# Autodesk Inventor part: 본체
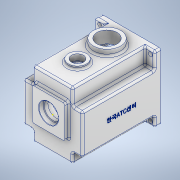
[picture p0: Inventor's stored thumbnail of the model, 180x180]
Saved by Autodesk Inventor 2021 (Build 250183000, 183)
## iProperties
Created: 2022-08
Part Number: 본체
Material: 알루미늄 6061
Document SubType Name: Modeling
Designer: Owner
Mass: 1403.85 g
Surface Area: 1175.53 cm^2
Volume: 519.945 cm^3
Density: 2.7 g/cm^3
Appearance: 알루미늄 - 평지
Author: Owner
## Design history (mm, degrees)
sketch "스케치1"
  geometry: L1 (-49, -55)-(49, -55); L2 (49, -55)-(49, 55); L3 (49, 55)-(-49, 55); L4 (-49, 55)-(-49, -55); L5 (-49, -55)-(49, 55); L6 (49, -55)-(-49, 55); 1 further point
  constraints: 12 end point, 2 midpoint, 2 parallel, 1 horizontal, 1 perpendicular
  dimensions: "d0" = 110 distance between parallel lines of L1 L3; "d1" = 98 distance between parallel lines of L2 L4
extrude "돌출1" new body sketch "스케치1" distance "d2" = 130; taper "d3" = 0 deg
sketch "스케치2"
  geometry: L1 (-49, -55)-(-49, 55) reference; L2 (-49, 55)-(-33, 55); L3 (-33, 55)-(-33, 28); L4 (-33, 28)-(-49, 28); L5 (-49, 28)-(-49, 55); 2 further points
  constraints: 8 end point, 2 parallel, 1 horizontal, 1 perpendicular
  dimensions: "d4" = 27 distance between parallel lines of L4 L2; "d5" = 16 distance between parallel lines of L3 L1
extrude "돌출2" cut sketch "스케치2" distance "d6" = 120; taper "d7" = 0 deg
sketch "스케치3"
  geometry: L1 (-27, -21)-(27, -21); L2 (27, -21)-(27, 33); L3 (27, 33)-(-27, 33); L4 (-27, 33)-(-27, -21); L5 (-49, -55)-(49, -55) reference; 2 further points
  constraints: 8 end point, 2 parallel, 1 horizontal, 1 midpoint, 1 perpendicular, 1 vertical alignment
  dimensions: "d8" = 54 distance between parallel lines of L1 L3; "d9" = 54 distance between parallel lines of L2 L4; "d191" = 88 distance between parallel lines of L5 L3
extrude "돌출3" join sketch "스케치3" distance "d10" = 7; taper "d11" = 0 deg
sketch "스케치4"
  geometry: L1 (82, -130)-(16, -130) reference; L2 (0, 0)-(98, 0) reference; C1 r 15 at (49, -89); C2 r 22.5 at (49, -40); 3 further points
  constraints: 2 centre point, 2 midpoint, 2 vertical alignment
  dimensions: "d12" = 30 diameter of C1; "d13" = 45 diameter of C2; "d14" = 49 distance of C2.centre C1.centre; "d15" = 40 distance from line of L2 C2.centre
extrude "돌출4" join sketch "스케치4" distance "d16" = 5; taper "d17" = 0 deg
extrude "돌출5" join sketch "스케치4" distance "d18" = 10; taper "d19" = 0 deg
sketch "스케치5"
  geometry: L1 (49, -55)-(-49, -55) reference; L2 (-49, -55)-(-33, -55); L3 (-33, -55)-(-33, -38); L4 (-33, -38)-(-49, -38); L5 (-49, -38)-(-49, -55); 2 further points
  constraints: 8 end point, 2 parallel, 1 horizontal, 1 perpendicular
  dimensions: "d20" = 17 distance between parallel lines of L1 L4; "d21" = 16 distance between parallel lines of L5 L3
extrude "돌출6" cut sketch "스케치5" distance "d22" = 120; taper "d23" = 0 deg
sketch "스케치7"
  geometry: 1 further point
sketch "스케치15"
  geometry: L1 (-49, -55)-(49, -55) reference; L2 (-23, 33.249)-(-23, 45); L3 (-23, 45)-(23, 45); L4 (23, 45)-(23, 33.249); A1 r 42 centre (0, -5) between (-25.375, 28.468) and (25.375, 28.468); A2 r 6 centre (-29, 33.249) between (-25.375, 28.468) and (-23, 33.249); A3 r 6 centre (29, 33.249) between (23, 33.249) and (25.375, 28.468); 3 further points
  constraints: 8 point on circle, 6 end point, 4 tangent, 3 centre point, 2 perpendicular, 2 point on line, 1 parallel, 1 vertical, 1 vertical alignment
  dimensions: "d33" = 50 distance from line of L1 A1.centre; "d34" = 84 diameter of A1; "d35" = 46 distance between parallel lines of L4 L2; "d37" = 6 radius of A2; "d38" = 6 radius of A3 (derived); "d196" = 50 distance from line of L3 A1.centre
extrude "돌출9" cut sketch "스케치15" distance "d39" = 121; taper "d40" = 0 deg
sketch "스케치17"
  geometry: L1 (23, 45)-(23, 33.249) reference; L2 (-23, 45)-(23, 45) reference; L3 (-23, 33.249)-(-23, 45) reference; L4 (-26, 33.249)-(-26, 48); L5 (-26, 48)-(26, 48); L6 (26, 48)-(26, 33.249); A1 r 42 centre (0, -5) between (-25.375, 28.468) and (25.375, 28.468) reference; A2 r 6 centre (-29, 33.249) between (-25.375, 28.468) and (-23, 33.249) reference; A3 r 6 centre (29, 33.249) between (23, 33.249) and (25.375, 28.468) reference; A4 r 45 centre (0, -5) between (-27.188, 30.859) and (27.188, 30.859); A5 r 3 centre (-29, 33.249) between (-27.188, 30.859) and (-26, 33.249); A6 r 3 centre (29, 33.249) between (26, 33.249) and (27.188, 30.859); 1 further point
  constraints: 6 end point, 6 point on circle, 3 centre point, 5 other
  dimensions: "d41" = 3 radial gap between concentric circles of A1 A4
extrude "돌출11" cut sketch "스케치17" distance "d44" = 9; taper "d45" = 0 deg
sketch "스케치19" dims "d52" = 72
  geometry: L1 (33, -55)-(-33, -55) reference; L2 (36, -1)-(41.809, -1); L3 (36, -9)-(41.809, -9); A1 r 42 centre (0, -5) between (-25.375, 28.468) and (25.375, 28.468) reference; A2 r 4 centre (36, -5) between (36, -1) and (36, -9); 2 further points
  constraints: 4 end point, 4 point on circle, 2 horizontal, 2 tangent, 1 centre point, 1 horizontal alignment, 1 parallel, 1 vertical alignment, 2 other
  dimensions: "d51" = 50 distance from line of L1 point (0, -5); "d53" = 8 diameter of A2
extrude "돌출12" join sketch "스케치19" distance "d55" = 121; taper "d56" = 0 deg
sketch "스케치21"
  geometry: A1 r 4 centre (36, -5) between (36, -1) and (36, -9) reference; 2 further points
  constraints: 1 coincident
hole "구멍1" sketch "스케치21" at (36, -5) diameter "d57" = 3.242; stored, may be unused: countersink angle "d61" = 90 deg, drill point angle "d63" = 118 deg; dims "d58" = 7, "d59" = 4, "d60" = 2, "d62" = 9
sketch "스케치24"
  geometry: C1 r 22.5 at (0, 0) reference; 2 further points
  constraints: 1 coincident
hole "구멍4" sketch "스케치24" at (0, 0) diameter "d78" = 33.376; stored, may be unused: countersink angle "d82" = 90 deg, drill point angle "d84" = 0 deg; dims "d79" = 70, "d80" = 4, "d81" = 2, "d83" = 77.3
sketch "스케치27"
  geometry: A1 r 21 centre (0, 6) between (8.978, -12.984) and (-8.978, -12.984); A2 r 15 centre (0, -25) between (-8.978, -12.984) and (8.978, -12.984); A3 r 4 centre (36, -5) between (36, -1) and (36, -9) reference; 1 further point
  constraints: 4 point on circle, 2 centre point, 2 vertical alignment
  dimensions: "d95" = 42 diameter of A1; "d96" = 30 diameter of A2; "d98" = 20 vertical distance of A2.centre A3.centre; "d102" = 11 vertical distance of A3.centre A1.centre
extrude "돌출13" join sketch "스케치27" distance "d100" = 7; taper "d101" = 0 deg
sketch "스케치30"
  geometry: L1 (-33, -55)-(33, -55) reference; C1 r 14 at (0, 6); 1 further point
  constraints: 1 centre point, 1 vertical alignment
  dimensions: "d103" = 61 distance from line of L1 C1.centre; "d104" = 28 diameter of C1
extrude "돌출14" cut sketch "스케치30" distance "d105" = 100; taper "d106" = 0 deg
sketch "스케치31"
  geometry: C1 r 14 at (0, 6) reference; 2 further points
  constraints: 1 coincident
hole "구멍6" sketch "스케치31" at (0, 6) diameter "d107" = 32; stored, may be unused: countersink angle "d111" = 90 deg, drill point angle "d113" = 0 deg; dims "d108" = 70, "d109" = 4, "d110" = 2, "d112" = 7
sketch "스케치32"
  geometry: C1 r 9.5 at (0, -25); A1 r 15 centre (0, -25) between (-8.978, -12.984) and (8.978, -12.984) reference; 1 further point
  constraints: 1 centre point, 1 coincident
  dimensions: "d114" = 19 diameter of C1
extrude "돌출15" cut sketch "스케치32" distance "d115" = 10; taper "d116" = 0 deg
sketch "스케치33"
  geometry: C1 r 9.5 at (0, -25) reference; 2 further points
  constraints: 1 coincident
hole "구멍7" sketch "스케치33" at (0, -25) diameter "d117" = 22; stored, may be unused: countersink angle "d121" = 90 deg, drill point angle "d123" = 0 deg; dims "d118" = 70, "d119" = 4, "d120" = 2, "d122" = 7
fillet "모깎기1" dims "d124" = 3
chamfer "모따기1" distance "d125" = 1; stored, may be unused: second distance "d126" = 2, angle "d127" = 45 deg
fillet "모깎기7" dims "d133" = 3
fillet "모깎기8" dims "d134" = 3
fillet "모깎기14" dims "d140" = 3
sketch "스케치34"
  geometry: C1 r 15 at (0, 0) reference; C2 r 10 at (0, 0); 1 further point
  constraints: 1 centre point, 1 coincident
  dimensions: "d141" = 20 diameter of C2
extrude "돌출16" cut sketch "스케치34" stored distance "d142" = 7; taper "d143" = 0 deg
fillet "모깎기15" dims "d144" = 3
sketch "스케치35"
  geometry: C1 r 10 at (23, -32) reference; 2 further points
  constraints: 1 coincident
hole "구멍8" sketch "스케치35" at (23, -32) diameter "d145" = 30; stored, may be unused: countersink angle "d149" = 90 deg, drill point angle "d151" = 0 deg; dims "d146" = 70, "d147" = 4, "d148" = 2, "d150" = 5
fillet "모깎기16" dims "d152" = 0.3
sketch "스케치36"
  geometry: L1 (49, 55)-(-49, 55) reference; L2 (-49, 55)-(-49, -55) reference; C1 r 3.5 at (-42, 48); 1 further point
  constraints: 1 centre point
  dimensions: "d153" = 7 distance from line of L1 C1.centre; "d154" = 7 distance from line of L2 C1.centre; "d155" = 7 diameter of C1
extrude "돌출17" cut sketch "스케치36" distance "d156" = 10; taper "d157" = 0 deg
sketch "스케치37"
  geometry: L1 (-130, 83)-(-130, 110) reference; L2 (-10, 83)-(-130, 83) reference; 2 further points
  constraints: 1 other
  dimensions: "d164" = 65 distance from line of L1 point (-65, 50); "d165" = 33 distance from line of L2 point (-65, 50)
feature "엠보싱1" sketch "스케치37" dims "d166" = 0.5, "d167" = 0
fillet "모깎기17" dims "d171" = 3
fillet "모깎기18" dims "d172" = 3
fillet "모깎기19" dims "d173" = 3
fillet "모깎기20" dims "d174" = 3
fillet "모깎기21" dims "d175" = 3
fillet "모깎기22" dims "d176" = 3
fillet "모깎기23" dims "d177" = 3
fillet "모깎기24" dims "d178" = 3
fillet "모깎기25" dims "d179" = 3
sketch "스케치38"
  geometry: C1 r 14 at (0, 6) reference; 2 further points
  constraints: 1 coincident
hole "구멍9" sketch "스케치38" at (0, 6) diameter "d180" = 35; stored, may be unused: countersink angle "d184" = 90 deg, drill point angle "d186" = 0 deg; dims "d181" = 70, "d182" = 4, "d183" = 2, "d185" = 10
fillet "모깎기26" dims "d187" = 3
fillet "모깎기27" dims "d188" = 3
fillet "모깎기28" dims "d189" = 3
fillet "모깎기29" dims "d190" = 3
chamfer "모따기3" distance "d192" = 0.8; stored, may be unused: second distance "d193" = 2, angle "d194" = 30 deg
fillet "모깎기30" dims "d195" = 3
fillet "모깎기31" dims "d197" = 3
chamfer "모따기4" distance "d198" = 1; stored, may be unused: second distance "d199" = 2, angle "d200" = 30 deg
node "솔리드1"
mirror "미러1"
mirror "미러3"
mirror "미러5"
pattern_linear "직사각형 패턴1" dims "d160" = 96
pattern_linear "직사각형 패턴2" dims "d163" = 84
feature "A9D066F2-1C7D-4E18-AEED-F7BC21143FA4" dims "d107" = 32, "d108" = 70, "d109" = 4, "d110" = 2, "d111" = 90 deg, "d112" = 7, "d113" = 0
